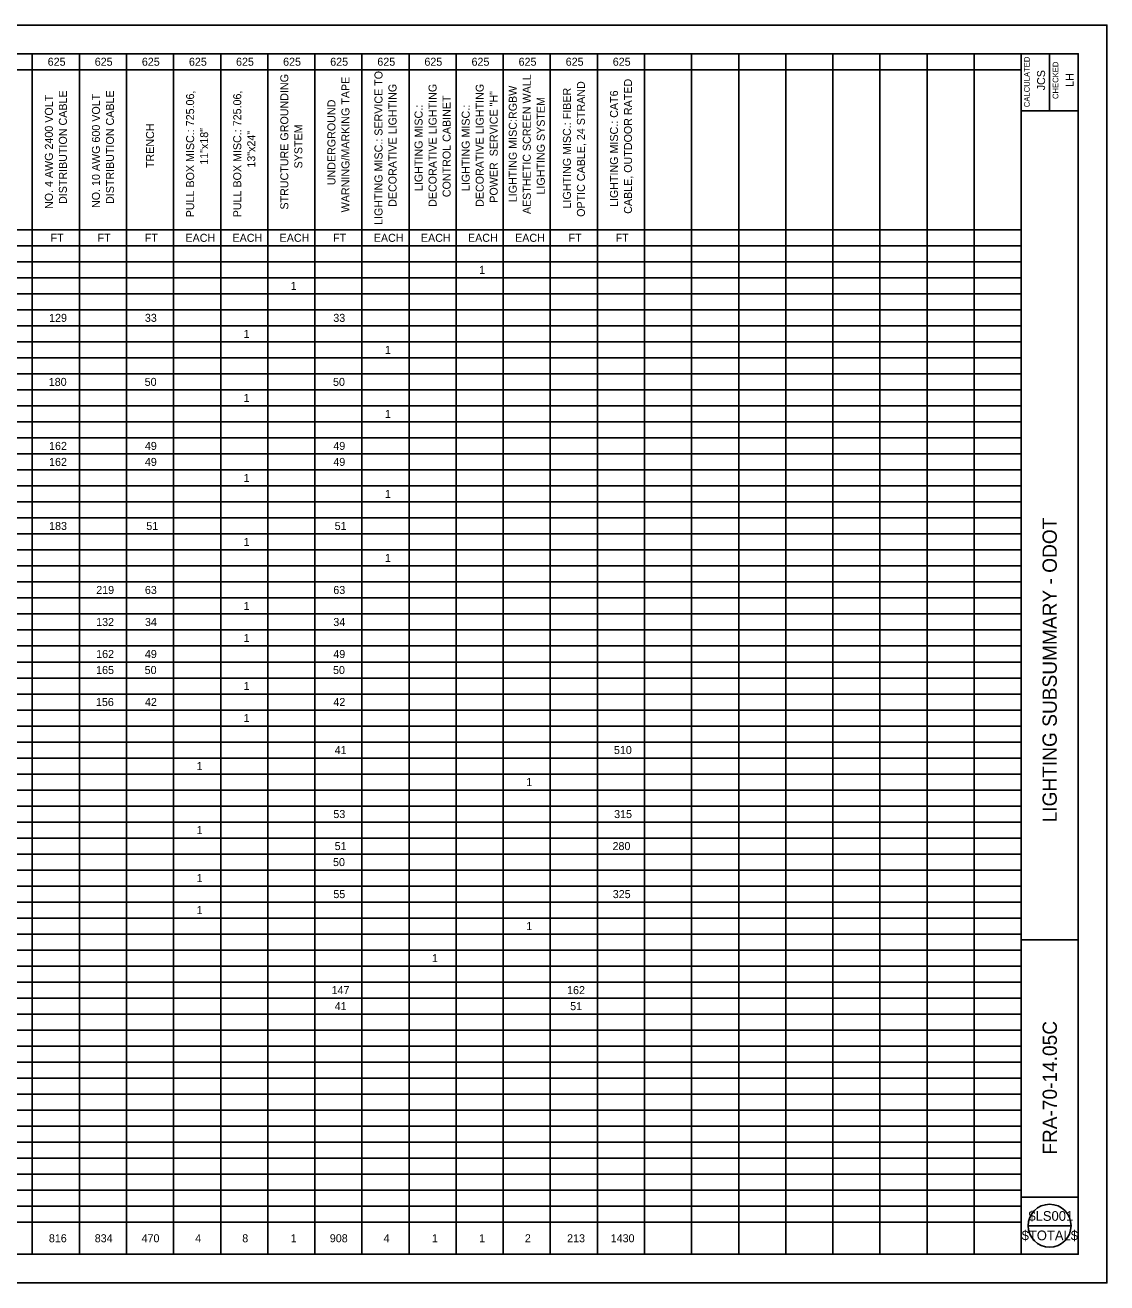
# Model space of a CAD drawing. Extents: x 0 to 34, y 0 to 22.
# Drawn here: x 15.08 to 34, y 0 to 22 of the extents above; entities that cross this region are included whole.
import ezdxf

# ---------------------------------------------------------------- set-up
doc = ezdxf.new("R2010")
doc.units = 0
for name, color, linetype in [('SH_Border', 7, 'Continuous'), ('SH_Cut_Line', 7, 'Continuous'), ('SH_Data', 7, 'Continuous'), ('SH_Text', 7, 'Continuous')]:
    doc.layers.add(name, color=color, linetype=linetype)

msp = doc.modelspace()

# ---------------------------------------------------------------- linework, layer by layer
at = {"layer": 'SH_Border'}
for p, q in [((32.5, 0.5), (32.5, 21.5)), ((33, 21.5), (33, 20.5)), ((32.5, 20.5), (33.5, 20.5)), ((32.5, 6), (33.5, 6)), ((32.5, 1.5), (33.5, 1.5))]:
    msp.add_line(p, q, dxfattribs=at)
msp.add_lwpolyline([(2, 21.5), (33.5, 21.5), (33.5, 0.5), (2, 0.5)], close=True, dxfattribs=at)
at = {"layer": 'SH_Cut_Line'}
msp.add_lwpolyline([(0, 0), (34, 0), (34, 22), (0, 22)], close=True, dxfattribs=at)
at = {"layer": 'SH_Data'}
for p, q in [((2, 21.5), (32.504, 21.5)), ((15.209, 21.5), (15.209, 0.5)), ((16.033, 21.5), (16.033, 0.5)), ((16.856, 21.5), (16.856, 0.5)), ((17.68, 21.5), (17.68, 0.5)), ((18.504, 21.5), (18.504, 0.5)), ((19.327, 21.5), (19.327, 0.5)), ((20.151, 21.5), (20.151, 0.5)), ((20.974, 21.5), (20.974, 0.5)), ((21.798, 21.5), (21.798, 0.5)), ((22.621, 21.5), (22.621, 0.5)), ((23.445, 21.5), (23.445, 0.5)), ((24.268, 21.5), (24.268, 0.5)), ((25.092, 21.5), (25.092, 0.5)), ((25.915, 21.5), (25.915, 0.5)), ((26.739, 21.5), (26.739, 0.5)), ((27.562, 21.5), (27.562, 0.5)), ((28.386, 21.5), (28.386, 0.5)), ((29.209, 21.5), (29.209, 0.5)), ((30.033, 21.5), (30.033, 0.5)), ((30.856, 21.5), (30.856, 0.5)), ((31.68, 21.5), (31.68, 0.5)), ((32.504, 21.5), (32.504, 0.5)), ((11.915, 21.22), (32.504, 21.22)), ((9.379, 18.42), (32.504, 18.42)), ((2, 18.14), (32.504, 18.14)), ((2, 17.86), (32.504, 17.86)), ((2, 17.58), (32.504, 17.58)), ((2, 17.3), (32.504, 17.3)), ((2, 17.02), (32.504, 17.02)), ((2, 16.74), (32.504, 16.74)), ((2, 16.46), (32.504, 16.46)), ((2, 16.18), (32.504, 16.18)), ((2, 15.9), (32.504, 15.9)), ((2, 15.62), (32.504, 15.62)), ((2, 15.34), (32.504, 15.34)), ((2, 15.06), (32.504, 15.06)), ((2, 14.78), (32.504, 14.78)), ((2, 14.5), (32.504, 14.5)), ((2, 14.22), (32.504, 14.22)), ((2, 13.94), (32.504, 13.94)), ((2, 13.66), (32.504, 13.66)), ((2, 13.38), (32.504, 13.38)), ((2, 13.1), (32.504, 13.1)), ((2, 12.82), (32.504, 12.82)), ((2, 12.54), (32.504, 12.54)), ((2, 12.26), (32.504, 12.26)), ((2, 11.98), (32.504, 11.98)), ((2, 11.7), (32.504, 11.7)), ((2, 11.42), (32.504, 11.42)), ((2, 11.14), (32.504, 11.14)), ((2, 10.86), (32.504, 10.86)), ((2, 10.58), (32.504, 10.58)), ((2, 10.3), (32.504, 10.3)), ((2, 10.02), (32.504, 10.02)), ((2, 9.74), (32.504, 9.74)), ((2, 9.46), (32.504, 9.46)), ((2, 9.18), (32.504, 9.18)), ((2, 8.9), (32.504, 8.9)), ((2, 8.62), (32.504, 8.62)), ((2, 8.34), (32.504, 8.34)), ((2, 8.06), (32.504, 8.06)), ((2, 7.78), (32.504, 7.78)), ((2, 7.5), (32.504, 7.5)), ((2, 7.22), (32.504, 7.22)), ((2, 6.94), (32.504, 6.94)), ((2, 6.66), (32.504, 6.66)), ((2, 6.38), (32.504, 6.38)), ((2, 6.1), (32.504, 6.1)), ((2, 5.82), (32.504, 5.82)), ((2, 5.54), (32.504, 5.54)), ((2, 5.26), (32.504, 5.26)), ((2, 4.98), (32.504, 4.98)), ((2, 4.7), (32.504, 4.7)), ((2, 4.42), (32.504, 4.42)), ((2, 4.14), (32.504, 4.14)), ((2, 3.86), (32.504, 3.86)), ((2, 3.58), (32.504, 3.58)), ((2, 3.3), (32.504, 3.3)), ((2, 3.02), (32.504, 3.02)), ((2, 2.74), (32.504, 2.74)), ((2, 2.46), (32.504, 2.46)), ((2, 2.18), (32.504, 2.18)), ((2, 1.9), (32.504, 1.9)), ((2, 1.62), (32.504, 1.62)), ((2, 1.34), (32.504, 1.34)), ((2, 1.06), (32.504, 1.06)), ((32.625, 1), (33.375, 1)), ((15.209, 0.5), (32.504, 0.5))]:
    msp.add_line(p, q, dxfattribs=at)
msp.add_circle((33, 1), 0.375, dxfattribs=at)

# ---------------------------------------------------------------- texts
for s, height, p in [('CALCULATED', 0.1, (32.652, 20.565)), ('CHECKED', 0.1, (33.152, 20.708)), ('JCS', 0.14, (32.92, 20.86)), ('LH', 0.14, (33.42, 20.922)), ('         LIGHTING SUBSUMMARY - ODOT         ', 0.25, (33.125, 7.219))]:
    msp.add_text(s, height=height, rotation=90, dxfattribs=at).set_placement(p)
for s, p in [('$LS001', (32.628, 1.085)), ('$TOTAL$', (32.51, 0.745))]:
    msp.add_text(s, height=0.17, dxfattribs=at).set_placement(p)
at = {"layer": 'SH_Text'}
for s, p in [('625', (15.478, 21.29)), ('625', (16.301, 21.29)), ('625', (17.125, 21.29)), ('625', (17.948, 21.29)), ('625', (18.772, 21.29)), ('625', (19.595, 21.29)), ('625', (20.419, 21.29)), ('625', (21.243, 21.29)), ('625', (22.066, 21.29)), ('625', (22.89, 21.29)), ('625', (23.713, 21.29)), ('625', (24.537, 21.29)), ('625', (25.36, 21.29)), ('FT', (15.528, 18.21)), ('FT', (16.351, 18.21)), ('FT', (17.175, 18.21)), ('EACH', (17.887, 18.21)), ('EACH', (18.71, 18.21)), ('EACH', (19.534, 18.21)), ('FT', (20.469, 18.21)), ('EACH', (21.181, 18.21)), ('EACH', (22.005, 18.21)), ('EACH', (22.828, 18.21)), ('EACH', (23.652, 18.21)), ('FT', (24.587, 18.21)), ('FT', (25.41, 18.21)), ('1', (23.022, 17.65)), ('1', (19.728, 17.37)), ('129', (15.503, 16.81)), ('33', (17.178, 16.81)), ('33', (20.473, 16.81)), ('1', (18.905, 16.53)), ('1', (21.375, 16.25)), ('180', (15.497, 15.69)), ('50', (17.174, 15.69)), ('50', (20.468, 15.69)), ('1', (18.905, 15.41)), ('1', (21.375, 15.13)), ('162', (15.502, 14.57)), ('49', (17.178, 14.57)), ('49', (20.473, 14.57)), ('162', (15.502, 14.29)), ('49', (17.178, 14.29)), ('49', (20.473, 14.29)), ('1', (18.905, 14.01)), ('1', (21.375, 13.73)), ('183', (15.503, 13.17)), ('51', (17.203, 13.17)), ('51', (20.497, 13.17)), ('1', (18.905, 12.89)), ('1', (21.375, 12.61)), ('219', (16.327, 12.05)), ('63', (17.178, 12.05)), ('63', (20.473, 12.05)), ('1', (18.905, 11.77)), ('132', (16.326, 11.49)), ('34', (17.179, 11.49)), ('34', (20.473, 11.49)), ('1', (18.905, 11.21)), ('162', (16.326, 10.93)), ('49', (17.178, 10.93)), ('49', (20.473, 10.93)), ('165', (16.325, 10.65)), ('50', (17.174, 10.65)), ('50', (20.468, 10.65)), ('1', (18.905, 10.37)), ('156', (16.322, 10.09)), ('42', (17.179, 10.09)), ('42', (20.474, 10.09)), ('1', (18.905, 9.81)), ('41', (20.497, 9.25)), ('510', (25.38, 9.25)), ('1', (18.081, 8.97)), ('1', (23.846, 8.69)), ('53', (20.474, 8.13)), ('315', (25.384, 8.13)), ('1', (18.081, 7.85)), ('51', (20.497, 7.57)), ('280', (25.356, 7.57)), ('50', (20.468, 7.29)), ('1', (18.081, 7.01)), ('55', (20.474, 6.73)), ('325', (25.36, 6.73)), ('1', (18.081, 6.45)), ('1', (23.846, 6.17)), ('1', (22.199, 5.61)), ('147', (20.443, 5.05)), ('162', (24.561, 5.05)), ('41', (20.497, 4.77)), ('51', (24.615, 4.77)), ('816', (15.499, 0.71)), ('834', (16.301, 0.71)), ('470', (17.12, 0.71)), ('4', (18.058, 0.71)), ('8', (18.881, 0.71)), ('1', (19.728, 0.71)), ('908', (20.412, 0.71)), ('4', (21.352, 0.71)), ('1', (22.199, 0.71)), ('1', (23.022, 0.71)), ('2', (23.823, 0.71)), ('213', (24.562, 0.71)), ('1430', (25.324, 0.71))]:
    msp.add_text(s, height=0.14, dxfattribs=at).set_placement(p)
for s, height, p in [('STRUCTURE GROUNDING', 0.14, (19.686, 18.774)), ('LIGHTING MISC.: SERVICE TO', 0.14, (21.333, 18.505)), ('AESTHETIC SCREEN WALL', 0.14, (23.926, 18.695)), ('WARNING/MARKING TAPE', 0.14, (20.755, 18.726)), ('DECORATIVE LIGHTING', 0.14, (21.578, 18.821)), ('DECORATIVE LIGHTING', 0.14, (22.279, 18.821)), ('DECORATIVE LIGHTING', 0.14, (23.103, 18.821)), ('LIGHTING MISC:RGBW', 0.14, (23.681, 18.902)), ('OPTIC CABLE, 24 STRAND', 0.14, (24.873, 18.647)), ('CABLE, OUTDOOR RATED', 0.14, (25.696, 18.7)), ('NO. 4 AWG 2400 VOLT', 0.14, (15.569, 18.784)), ('DISTRIBUTION CABLE', 0.14, (15.814, 18.872)), ('NO. 10 AWG 600 VOLT', 0.14, (16.392, 18.802)), ('DISTRIBUTION CABLE', 0.14, (16.637, 18.872)), ('PULL BOX MISC.: 725.06,', 0.14, (18.039, 18.639)), ('PULL BOX MISC.: 725.06,', 0.14, (18.863, 18.639)), ('UNDERGROUND', 0.14, (20.51, 19.2)), ('CONTROL CABINET', 0.14, (22.524, 18.991)), ('POWER  SERVICE "H"', 0.14, (23.348, 18.894)), ('LIGHTING SYSTEM', 0.14, (24.171, 19.037)), ('LIGHTING MISC.: FIBER', 0.14, (24.628, 18.793)), ('LIGHTING MISC.: CAT6', 0.14, (25.451, 18.819)), ('LIGHTING MISC.:', 0.14, (22.034, 19.098)), ('LIGHTING MISC.:', 0.14, (22.858, 19.098)), ('TRENCH', 0.14, (17.338, 19.501)), ('SYSTEM', 0.14, (19.931, 19.494)), ('11"x18"', 0.14, (18.284, 19.558)), ('13"x24"', 0.14, (19.108, 19.508)), ('FRA-70-14.05C', 0.24987, (33.127, 2.241))]:
    msp.add_text(s, height=height, rotation=90, dxfattribs=at).set_placement(p)

doc.saveas('drawing.dxf')
